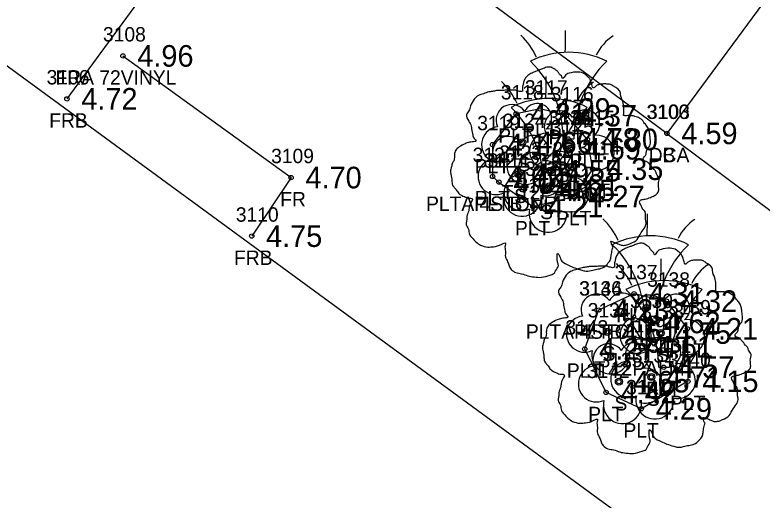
# Model space of a CAD drawing. Extents: x 2608598 to 2610682, y 641451 to 643526.
# Drawn here: x 2609915.7 to 2609967.6, y 642037.7 to 642071.3 of the extents above; entities that cross this region are included whole.
import ezdxf

# ---------------------------------------------------------------- set-up
doc = ezdxf.new("R2010")
doc.units = 0
for name, color, linetype in [('RD_EX_Bldg', 7, 'Continuous'), ('RD_EX_Bldg_txCode', 7, 'Continuous'), ('RD_EX_BldgApp', 7, 'Continuous'), ('RD_EX_BldgApp_txCode', 7, 'Continuous'), ('RD_EX_Conc', 7, 'Continuous'), ('RD_EX_Conc_txCode', 7, 'Continuous'), ('RD_EX_Fence_Other', 7, 'Continuous'), ('RD_EX_Fence_Other_txCode', 7, 'Continuous'), ('RD_EX_TX_Bldg_ELEV', 7, 'Continuous'), ('RD_EX_TX_BldgApp_ELEV', 7, 'Continuous'), ('RD_EX_TX_Conc_ELEV', 7, 'Continuous'), ('RD_EX_TX_Fence_Other_ELEV', 7, 'Continuous'), ('RD_EX_TX_VEG_ELEV', 7, 'Continuous'), ('RD_EX_VEG', 7, 'Continuous'), ('RD_EX_VEG_txCode', 7, 'Continuous'), ('RD_SMD_Locator', 7, 'Continuous')]:
    doc.layers.add(name, color=color, linetype=linetype)

msp = doc.modelspace()

# ---------------------------------------------------------------- linework, layer by layer
at = {"layer": 'RD_EX_Bldg'}
for points in [[(2609925.869, 642126.537), (2609978.853, 642087.305), (2609961.016, 642063.114), (2609908.032, 642102.345), (2609925.869, 642126.537)], [(2609909.121, 642072.222), (2609960.739, 642034.485), (2609938.692, 642004.745), (2609887.073, 642042.482), (2609909.121, 642072.222)]]:
    msp.add_lwpolyline(points, dxfattribs=at)
at = {"layer": 'RD_EX_BldgApp'}
for p, q in [((2609953.807, 642062.744), (2609954.557, 642062.744)), ((2609952.457, 642059.539), (2609953.207, 642059.539)), ((2609959.492, 642050.005), (2609960.242, 642050.005)), ((2609960.442, 642046.891), (2609961.192, 642046.891))]:
    msp.add_line(p, q, dxfattribs=at)
for points in [[(2609949.341, 642059.731), (2609951.701, 642058.031), (2609954.562, 642058.731), (2609955.861, 642060.629), (2609955.487, 642062.692), (2609954.03, 642064.344), (2609952.204, 642064.807), (2609950.538, 642064.47), (2609948.897, 642062.333), (2609948.903, 642060.121), (2609949.341, 642059.731)], [(2609956.277, 642050.851), (2609958.732, 642051.985), (2609960.983, 642051.466), (2609962.44, 642049.545), (2609962.47, 642045.898), (2609959.236, 642043.994), (2609956.787, 642045.128), (2609955.306, 642048.145), (2609956.277, 642050.851)]]:
    msp.add_lwpolyline(points, dxfattribs=at)
for centre, radius, start, end in [((2609916.101, 642070.082), 37.876, 358.0671, 0.2715), ((2609947.49, 642066.387), 4.895, 24.3279, 46.2665), ((2609959.071, 642067.137), 3.283, 123.2906, 154.4886), ((2609954.182, 642062.744), 5.997, 63.7794, 116.2206), ((2609946.307, 642062.744), 7.5, 0, 45.8366), ((2609962.057, 642062.744), 7.5, 134.1634, 180), ((2609914.75, 642066.877), 37.876, 358.0671, 0.2715), ((2609946.139, 642063.182), 4.895, 24.3279, 46.2665), ((2609957.72, 642063.933), 3.283, 123.2906, 154.4886), ((2609952.832, 642059.539), 5.997, 63.7794, 116.2206), ((2609944.957, 642059.539), 7.5, 0, 45.8366), ((2609960.707, 642059.539), 7.5, 134.1634, 180), ((2609953.175, 642053.648), 4.895, 24.3279, 46.2665), ((2609921.786, 642057.343), 37.876, 358.0671, 0.2715), ((2609964.756, 642054.398), 3.283, 123.2906, 154.4886), ((2609959.867, 642050.005), 5.997, 63.7794, 116.2206), ((2609951.992, 642050.005), 7.5, 0, 45.8366), ((2609967.742, 642050.005), 7.5, 134.1634, 180), ((2609954.125, 642050.534), 4.895, 24.3279, 46.2665), ((2609922.736, 642054.229), 37.876, 358.0671, 0.2715), ((2609965.705, 642051.284), 3.283, 123.2906, 154.4886), ((2609960.817, 642046.891), 5.997, 63.7794, 116.2206), ((2609952.942, 642046.891), 7.5, 0, 45.8366), ((2609968.692, 642046.891), 7.5, 134.1634, 180)]:
    msp.add_arc(centre, radius, start, end, dxfattribs=at)
at = {"layer": 'RD_EX_Conc'}
msp.add_lwpolyline([(2609961.016, 642063.114), (2609970.253, 642056.24), (2609973.77, 642053.725), (2609978.671, 642051.077), (2609980.569, 642050.362), (2609982.905, 642049.619), (2609986.846, 642049.978), (2609990.334, 642051.359), (2609992.677, 642052.953), (2609997.86, 642057.875), (2610001.755, 642060.528), (2610004.736, 642061.459), (2610008.347, 642061.293), (2610011.93, 642059.679), (2610016.967, 642054.45), (2610017.895, 642052.738)], dxfattribs=at)
at = {"layer": 'RD_EX_Fence_Other'}
msp.add_line((2609932.063, 642082.907), (2609919.333, 642065.511), dxfattribs=at)
msp.add_lwpolyline([(2609923.224, 642068.493), (2609934.905, 642060.046), (2609932.168, 642055.98)], dxfattribs=at)
at = {"layer": 'RD_EX_VEG'}
for centre, radius in [((2609950.956, 642062.485), 0.25), ((2609954.298, 642062.045), 0.25), ((2609952.914, 642060.524), 0.25), ((2609950.711, 642060.278), 0.25), ((2609952.901, 642060.506), 0.0001), ((2609952.511, 642059.16), 0.25), ((2609956.856, 642049.333), 0.25), ((2609960.568, 642049.251), 0.25), ((2609959.304, 642048.295), 0.25), ((2609959.291, 642048.276), 0.0001), ((2609959.93, 642046.198), 0.25), ((2609957.68, 642045.875), 0.25)]:
    msp.add_circle(centre, radius, dxfattribs=at)
for centre, radius, start, end in [((2609950.235, 642064.032), 1.084, 34.9763, 204.756), ((2609952.002, 642064.187), 0.995, 308.7626, 152.0467), ((2609953.577, 642063.592), 1.084, 34.9763, 204.756), ((2609955.343, 642063.747), 0.995, 308.7626, 152.0467), ((2609949.393, 642062.329), 1.257, 96.4518, 294.734), ((2609952.796, 642062.206), 1.218, 256.5667, 98.1046), ((2609949.99, 642061.825), 1.084, 34.9763, 204.756), ((2609951.756, 642061.98), 0.995, 308.7626, 152.0467), ((2609952.734, 642061.889), 1.257, 96.4518, 294.734), ((2609956.137, 642061.765), 1.218, 256.5667, 98.1046), ((2609951.79, 642060.707), 1.084, 34.9763, 204.756), ((2609953.556, 642060.862), 0.995, 308.7626, 152.0467), ((2609949.147, 642060.122), 1.257, 96.4518, 294.734), ((2609951.202, 642060.889), 1.318, 166.8827, 5.7589), ((2609952.551, 642059.998), 1.218, 256.5667, 98.1046), ((2609954.543, 642060.448), 1.318, 166.8827, 5.7589), ((2609950.947, 642059.005), 1.257, 96.4518, 294.734), ((2609954.351, 642058.881), 1.218, 256.5667, 98.1046), ((2609950.957, 642058.681), 1.318, 166.8827, 5.7589), ((2609952.756, 642057.564), 1.318, 166.8827, 5.7589), ((2609956.135, 642050.88), 1.084, 34.9763, 204.756), ((2609957.902, 642051.035), 0.995, 308.7626, 152.0467), ((2609961.614, 642050.953), 0.995, 308.7626, 152.0467), ((2609959.847, 642050.798), 1.084, 34.9763, 204.756), ((2609955.293, 642049.178), 1.257, 96.4518, 294.734), ((2609959.005, 642049.096), 1.257, 96.4518, 294.734), ((2609958.696, 642049.054), 1.218, 256.5667, 98.1046), ((2609962.408, 642048.972), 1.218, 256.5667, 98.1046), ((2609959.209, 642047.745), 1.084, 34.9763, 204.756), ((2609960.975, 642047.9), 0.995, 308.7626, 152.0467), ((2609956.959, 642047.422), 1.084, 34.9763, 204.756), ((2609958.725, 642047.577), 0.995, 308.7626, 152.0467), ((2609957.102, 642047.737), 1.318, 166.8827, 5.7589), ((2609960.814, 642047.655), 1.318, 166.8827, 5.7589), ((2609958.366, 642046.043), 1.257, 96.4518, 294.734), ((2609956.116, 642045.72), 1.257, 96.4518, 294.734), ((2609959.519, 642045.596), 1.218, 256.5667, 98.1046), ((2609961.77, 642045.919), 1.218, 256.5667, 98.1046), ((2609960.176, 642044.602), 1.318, 166.8827, 5.7589), ((2609957.925, 642044.279), 1.318, 166.8827, 5.7589)]:
    msp.add_arc(centre, radius, start, end, dxfattribs=at)
for points in [[(2609953.046, 642067.692), (2609952.746, 642067.717), (2609952.421, 642067.617), (2609952.171, 642067.517), (2609951.946, 642067.442), (2609951.721, 642067.342), (2609951.422, 642067.167), (2609951.197, 642066.967), (2609951.072, 642066.717), (2609951.022, 642066.492), (2609950.972, 642066.217), (2609950.972, 642066.042), (2609950.847, 642066.017), (2609950.697, 642066.042), (2609950.447, 642066.117), (2609950.197, 642066.117), (2609949.947, 642066.117), (2609949.597, 642066.092), (2609949.247, 642066.092), (2609948.973, 642066.042), (2609948.648, 642065.992), (2609948.273, 642065.867), (2609947.923, 642065.742), (2609947.623, 642065.493), (2609947.373, 642065.018), (2609947.248, 642064.668), (2609947.098, 642064.418), (2609947.248, 642063.968), (2609947.423, 642063.618), (2609947.448, 642063.418), (2609947.523, 642062.994), (2609947.623, 642062.769), (2609947.748, 642062.569), (2609947.673, 642062.544), (2609947.298, 642062.494), (2609946.998, 642062.394), (2609946.574, 642062.169), (2609946.349, 642061.944), (2609946.249, 642061.619), (2609946.224, 642061.269), (2609946.124, 642061.07), (2609946.049, 642060.795), (2609946.024, 642060.72), (2609945.974, 642060.395), (2609946.074, 642059.945), (2609946.099, 642059.595), (2609946.224, 642059.37), (2609946.374, 642059.195), (2609946.549, 642058.945), (2609946.948, 642058.721), (2609947.273, 642058.621), (2609947.473, 642058.596), (2609947.298, 642058.096), (2609947.248, 642057.746), (2609947.123, 642057.346), (2609947.123, 642057.271), (2609947.073, 642056.796), (2609947.223, 642056.471), (2609947.298, 642056.097), (2609947.473, 642055.872), (2609947.748, 642055.572), (2609948.073, 642055.347), (2609948.573, 642055.222), (2609948.973, 642055.247), (2609949.547, 642055.422), (2609949.797, 642055.497), (2609949.772, 642055.322), (2609949.797, 642054.947), (2609949.797, 642054.522), (2609949.947, 642054.198), (2609950.047, 642053.923), (2609950.197, 642053.673), (2609950.522, 642053.448), (2609950.922, 642053.373), (2609951.347, 642053.223), (2609951.796, 642053.148), (2609952.296, 642053.123), (2609952.896, 642053.273), (2609953.171, 642053.398), (2609953.271, 642053.573), (2609953.471, 642053.948), (2609953.421, 642054.173), (2609953.446, 642054.772), (2609953.546, 642054.597), (2609953.721, 642054.247), (2609954.22, 642053.948), (2609954.62, 642053.773), (2609955.095, 642053.623), (2609955.395, 642053.548), (2609955.87, 642053.623), (2609956.244, 642053.698), (2609956.619, 642053.823), (2609956.919, 642054.098), (2609957.094, 642054.372), (2609957.144, 642054.647), (2609957.219, 642055.022), (2609957.269, 642055.197)], [(2609957.269, 642055.197), (2609957.194, 642055.372), (2609957.144, 642055.622), (2609957.219, 642055.597), (2609957.394, 642055.547), (2609957.669, 642055.422), (2609957.894, 642055.347), (2609958.219, 642055.372), (2609958.493, 642055.472), (2609958.943, 642055.747), (2609959.218, 642056.222), (2609959.493, 642056.621), (2609959.568, 642056.946), (2609959.518, 642057.171), (2609959.493, 642057.671), (2609959.293, 642057.921), (2609959.243, 642058.046), (2609959.143, 642058.446), (2609959.218, 642058.496), (2609959.493, 642058.546), (2609959.868, 642058.671), (2609960.143, 642058.795), (2609960.368, 642058.97), (2609960.443, 642059.195), (2609960.418, 642059.595), (2609960.468, 642059.995), (2609960.393, 642060.145), (2609960.293, 642060.295), (2609960.218, 642060.495), (2609960.068, 642060.645), (2609959.968, 642060.795), (2609959.868, 642060.895), (2609959.743, 642061.045), (2609959.568, 642061.169), (2609959.418, 642061.219), (2609959.368, 642061.369), (2609959.518, 642061.569), (2609959.568, 642061.669), (2609959.593, 642061.894), (2609959.818, 642062.244), (2609959.868, 642062.644), (2609959.818, 642063.069), (2609959.768, 642063.344), (2609959.618, 642063.618), (2609959.418, 642063.868), (2609959.293, 642064.043), (2609959.118, 642064.168), (2609958.793, 642064.293), (2609958.543, 642064.343), (2609958.194, 642064.343), (2609957.994, 642064.393), (2609958.019, 642064.443), (2609958.019, 642064.593), (2609958.019, 642064.868), (2609957.944, 642065.318), (2609957.794, 642065.817), (2609957.794, 642065.842), (2609957.694, 642066.092), (2609957.469, 642066.292), (2609957.294, 642066.392), (2609957.094, 642066.517), (2609956.844, 642066.542), (2609956.544, 642066.542), (2609956.269, 642066.492), (2609956.069, 642066.392), (2609955.895, 642066.267), (2609955.82, 642066.417), (2609955.72, 642066.717), (2609955.67, 642066.867), (2609955.52, 642067.042), (2609955.295, 642067.242), (2609954.845, 642067.367), (2609954.22, 642067.292), (2609953.92, 642067.092), (2609953.77, 642066.917), (2609953.721, 642067.042), (2609953.521, 642067.242), (2609953.421, 642067.417), (2609953.246, 642067.542), (2609953.096, 642067.642), (2609952.996, 642067.692)], [(2609959.435, 642055.462), (2609959.136, 642055.487), (2609958.811, 642055.387), (2609958.561, 642055.287), (2609958.336, 642055.212), (2609958.111, 642055.112), (2609957.811, 642054.937), (2609957.586, 642054.737), (2609957.461, 642054.487), (2609957.411, 642054.262), (2609957.361, 642053.988), (2609957.361, 642053.813), (2609957.236, 642053.788), (2609957.086, 642053.813), (2609956.837, 642053.888), (2609956.587, 642053.888), (2609956.337, 642053.888), (2609955.987, 642053.863), (2609955.637, 642053.863), (2609955.362, 642053.813), (2609955.037, 642053.763), (2609954.663, 642053.638), (2609954.313, 642053.513), (2609954.013, 642053.263), (2609953.763, 642052.788), (2609953.638, 642052.438), (2609953.488, 642052.188), (2609953.638, 642051.739), (2609953.813, 642051.389), (2609953.838, 642051.189), (2609953.913, 642050.764), (2609954.013, 642050.539), (2609954.138, 642050.339), (2609954.063, 642050.314), (2609953.688, 642050.264), (2609953.388, 642050.164), (2609952.963, 642049.939), (2609952.738, 642049.714), (2609952.638, 642049.39), (2609952.613, 642049.04), (2609952.514, 642048.84), (2609952.439, 642048.565), (2609952.414, 642048.49), (2609952.364, 642048.165), (2609952.464, 642047.715), (2609952.489, 642047.365), (2609952.613, 642047.141), (2609952.763, 642046.966), (2609952.938, 642046.716), (2609953.338, 642046.491), (2609953.663, 642046.391), (2609953.863, 642046.366), (2609953.688, 642045.866), (2609953.638, 642045.516), (2609953.513, 642045.116), (2609953.513, 642045.042), (2609953.463, 642044.567), (2609953.613, 642044.242), (2609953.688, 642043.867), (2609953.863, 642043.642), (2609954.138, 642043.342), (2609954.463, 642043.117), (2609954.962, 642042.992), (2609955.362, 642043.017), (2609955.937, 642043.192), (2609956.187, 642043.267), (2609956.162, 642043.092), (2609956.187, 642042.717), (2609956.187, 642042.293), (2609956.337, 642041.968), (2609956.437, 642041.693), (2609956.587, 642041.443), (2609956.912, 642041.218), (2609957.311, 642041.143), (2609957.736, 642040.993), (2609958.186, 642040.918), (2609958.686, 642040.893), (2609959.286, 642041.043), (2609959.56, 642041.168), (2609959.66, 642041.343), (2609959.86, 642041.718), (2609959.81, 642041.943), (2609959.835, 642042.543), (2609959.935, 642042.368), (2609960.11, 642042.018), (2609960.61, 642041.718), (2609961.01, 642041.543), (2609961.485, 642041.393), (2609961.784, 642041.318), (2609962.259, 642041.393), (2609962.634, 642041.468), (2609963.009, 642041.593), (2609963.309, 642041.868), (2609963.484, 642042.143), (2609963.534, 642042.418), (2609963.609, 642042.792), (2609963.659, 642042.967)], [(2609963.659, 642042.967), (2609963.584, 642043.142), (2609963.534, 642043.392), (2609963.609, 642043.367), (2609963.784, 642043.317), (2609964.058, 642043.192), (2609964.283, 642043.117), (2609964.608, 642043.142), (2609964.883, 642043.242), (2609965.333, 642043.517), (2609965.608, 642043.992), (2609965.883, 642044.392), (2609965.958, 642044.717), (2609965.908, 642044.942), (2609965.883, 642045.441), (2609965.683, 642045.691), (2609965.633, 642045.816), (2609965.533, 642046.216), (2609965.608, 642046.266), (2609965.883, 642046.316), (2609966.257, 642046.441), (2609966.532, 642046.566), (2609966.757, 642046.741), (2609966.832, 642046.966), (2609966.807, 642047.365), (2609966.857, 642047.765), (2609966.782, 642047.915), (2609966.682, 642048.065), (2609966.607, 642048.265), (2609966.457, 642048.415), (2609966.357, 642048.565), (2609966.257, 642048.665), (2609966.133, 642048.815), (2609965.958, 642048.94), (2609965.808, 642048.99), (2609965.758, 642049.14), (2609965.908, 642049.34), (2609965.958, 642049.44), (2609965.983, 642049.664), (2609966.208, 642050.014), (2609966.257, 642050.414), (2609966.208, 642050.839), (2609966.158, 642051.114), (2609966.008, 642051.389), (2609965.808, 642051.639), (2609965.683, 642051.814), (2609965.508, 642051.938), (2609965.183, 642052.063), (2609964.933, 642052.113), (2609964.583, 642052.113), (2609964.383, 642052.163), (2609964.408, 642052.213), (2609964.408, 642052.363), (2609964.408, 642052.638), (2609964.333, 642053.088), (2609964.183, 642053.588), (2609964.183, 642053.613), (2609964.083, 642053.863), (2609963.859, 642054.063), (2609963.684, 642054.162), (2609963.484, 642054.287), (2609963.234, 642054.312), (2609962.934, 642054.312), (2609962.659, 642054.262), (2609962.459, 642054.162), (2609962.284, 642054.038), (2609962.209, 642054.187), (2609962.109, 642054.487), (2609962.059, 642054.637), (2609961.909, 642054.812), (2609961.685, 642055.012), (2609961.235, 642055.137), (2609960.61, 642055.062), (2609960.31, 642054.862), (2609960.16, 642054.687), (2609960.11, 642054.812), (2609959.91, 642055.012), (2609959.81, 642055.187), (2609959.635, 642055.312), (2609959.485, 642055.412), (2609959.385, 642055.462)]]:
    msp.add_spline(points, degree=3, dxfattribs=at)
at = {"layer": 'RD_SMD_Locator'}
for centre in [(2609923.224, 642068.493), (2609919.333, 642065.511), (2609952.204, 642064.807), (2609950.538, 642064.47), (2609954.03, 642064.344), (2609954.154, 642062.726), (2609955.487, 642062.692), (2609961.016, 642063.114), (2609961.016, 642063.114), (2609948.897, 642062.333), (2609950.956, 642062.485), (2609954.298, 642062.045), (2609955.861, 642060.629), (2609948.903, 642060.121), (2609950.711, 642060.278), (2609952.914, 642060.524), (2609934.905, 642060.046), (2609949.341, 642059.731), (2609949.341, 642059.731), (2609952.511, 642059.16), (2609952.804, 642059.521), (2609954.562, 642058.731), (2609951.701, 642058.031), (2609932.168, 642055.98), (2609958.732, 642051.985), (2609960.983, 642051.466), (2609956.277, 642050.851), (2609956.277, 642050.851), (2609959.839, 642049.987), (2609956.856, 642049.333), (2609960.568, 642049.251), (2609962.44, 642049.545), (2609955.306, 642048.145), (2609959.304, 642048.295), (2609960.789, 642046.873), (2609959.93, 642046.198), (2609957.68, 642045.875), (2609962.47, 642045.898), (2609956.787, 642045.128), (2609959.236, 642043.994)]:
    msp.add_circle(centre, 0.15, dxfattribs=at)

# ---------------------------------------------------------------- texts
at = {"layer": 'RD_EX_Bldg_txCode'}
for s, p in [('3100', (2609959.591, 642064.114)), ('B', (2609960.709, 642061.114))]:
    msp.add_text(s, height=1, dxfattribs=at).set_placement(p)
at = {"layer": 'RD_EX_BldgApp_txCode'}
for s, p in [('3118', (2609949.475, 642065.47)), ('3117', (2609951.141, 642065.807)), ('3116', (2609952.943, 642065.344)), ('3126', (2609952.784, 642063.726)), ('3115', (2609954.424, 642063.692)), ('3119', (2609947.834, 642063.333)), ('PLT', (2609949.294, 642062.47)), ('PLT', (2609950.96, 642062.807)), ('PLT', (2609952.786, 642062.344)), ('3114', (2609954.798, 642061.629)), ('3120', (2609947.517, 642061.121)), ('PLT', (2609947.653, 642060.333)), ('3121', (2609948.278, 642060.731)), ('3111', (2609948.561, 642060.731)), ('3127', (2609951.458, 642060.521)), ('FLT', (2609952.934, 642060.726)), ('PLT', (2609954.243, 642060.692)), ('3113', (2609953.499, 642059.731)), ('3112', (2609950.638, 642059.031)), ('PLT', (2609954.617, 642058.629)), ('PLTA 4STONE', (2609944.282, 642057.731)), ('PLTB', (2609947.624, 642057.731)), ('PLT', (2609947.659, 642058.121)), ('FLT', (2609951.584, 642057.521)), ('PLT', (2609953.318, 642056.731)), ('PLT', (2609950.457, 642056.031)), ('3137', (2609957.386, 642052.985)), ('3138', (2609959.637, 642052.466)), ('3136', (2609954.907, 642051.851)), ('3144', (2609954.931, 642051.851)), ('3130', (2609958.454, 642050.987)), ('3139', (2609961.093, 642050.545)), ('PLT', (2609957.488, 642049.985)), ('PLT', (2609959.739, 642049.466)), ('PLTA 4STONE', (2609951.218, 642048.851)), ('3143', (2609953.959, 642049.145)), ('PLTB', (2609954.561, 642048.851)), ('FLT', (2609958.619, 642047.987)), ('3131', (2609959.726, 642047.873)), ('PLT', (2609961.196, 642047.545)), ('3140', (2609961.084, 642046.898)), ('PLT', (2609954.062, 642046.145)), ('3142', (2609955.44, 642046.128)), ('3141', (2609958.173, 642044.994)), ('FLT', (2609959.569, 642044.873)), ('PLT', (2609961.226, 642043.898)), ('PLT', (2609955.543, 642043.128)), ('PLT', (2609957.992, 642041.994))]:
    msp.add_text(s, height=1, dxfattribs=at).set_placement(p)
at = {"layer": 'RD_EX_Conc_txCode'}
for s, p in [('3103', (2609959.631, 642064.114)), ('DCA', (2609959.749, 642061.114))]:
    msp.add_text(s, height=1, dxfattribs=at).set_placement(p)
at = {"layer": 'RD_EX_Fence_Other_txCode'}
for s, p in [('3108', (2609921.838, 642069.493)), ('3106', (2609917.923, 642066.511)), ('FRA 72VINYL', (2609918.539, 642066.493)), ('FRB', (2609918.104, 642063.511)), ('3109', (2609933.519, 642061.046)), ('FR', (2609934.149, 642058.046)), ('3110', (2609931.066, 642056.98)), ('FRB', (2609930.94, 642053.98))]:
    msp.add_text(s, height=1, dxfattribs=at).set_placement(p)
at = {"layer": 'RD_EX_TX_Bldg_ELEV'}
msp.add_text('4.59', height=1.5, dxfattribs=at).set_placement((2609962.016, 642062.364))
at = {"layer": 'RD_EX_TX_BldgApp_ELEV'}
for s, p in [('4.29', (2609953.204, 642064.057)), ('4.21', (2609951.538, 642063.72)), ('4.37', (2609955.03, 642063.594)), ('4.78', (2609955.154, 642061.976)), ('4.30', (2609956.487, 642061.942)), ('4.17', (2609949.897, 642061.583)), ('4.35', (2609956.861, 642059.879)), ('4.02', (2609949.903, 642059.371)), ('4.01', (2609950.341, 642058.981)), ('4.01', (2609950.341, 642058.981)), ('4.61', (2609953.804, 642058.771)), ('4.27', (2609955.562, 642057.981)), ('4.21', (2609952.701, 642057.281)), ('4.31', (2609959.732, 642051.235)), ('4.32', (2609961.983, 642050.716)), ('4.23', (2609957.277, 642050.101)), ('4.23', (2609957.277, 642050.101)), ('4.62', (2609960.839, 642049.237)), ('4.21', (2609963.44, 642048.795)), ('4.27', (2609956.306, 642047.395)), ('4.57', (2609961.789, 642046.123)), ('4.15', (2609963.47, 642045.148)), ('4.42', (2609957.787, 642044.378)), ('4.29', (2609960.236, 642043.244))]:
    msp.add_text(s, height=1.5, dxfattribs=at).set_placement(p)
at = {"layer": 'RD_EX_TX_Conc_ELEV'}
msp.add_text('4.59', height=1.5, dxfattribs=at).set_placement((2609962.016, 642062.364))
at = {"layer": 'RD_EX_TX_Fence_Other_ELEV'}
for s, p in [('4.96', (2609924.224, 642067.743)), ('4.72', (2609920.333, 642064.761)), ('4.70', (2609935.905, 642059.296)), ('4.75', (2609933.168, 642055.23))]:
    msp.add_text(s, height=1.5, dxfattribs=at).set_placement(p)
at = {"layer": 'RD_EX_TX_VEG_ELEV'}
for s, p in [('4.66', (2609951.956, 642061.735)), ('4.69', (2609955.298, 642061.295)), ('4.55', (2609953.914, 642059.774)), ('4.59', (2609951.711, 642059.528)), ('4.65', (2609953.511, 642058.41)), ('4.61', (2609957.856, 642048.583)), ('4.75', (2609961.568, 642048.501)), ('4.61', (2609960.304, 642047.545)), ('4.71', (2609960.93, 642045.448)), ('4.65', (2609958.68, 642045.125))]:
    msp.add_text(s, height=1.5, dxfattribs=at).set_placement(p)
at = {"layer": 'RD_EX_VEG_txCode'}
for s, p in [('3124', (2609949.61, 642063.485)), ('3125', (2609952.951, 642063.045)), ('3123', (2609949.365, 642061.278)), ('3128', (2609951.567, 642061.524)), ('S', (2609950.649, 642060.485)), ('3122', (2609951.164, 642060.16)), ('S', (2609953.991, 642060.045)), ('T 12PALM', (2609949.544, 642058.524)), ('S', (2609950.404, 642058.278)), ('S', (2609952.204, 642057.16)), ('3134', (2609955.51, 642050.333)), ('3133', (2609959.222, 642050.251)), ('3129', (2609957.957, 642049.295)), ('S', (2609956.549, 642047.333)), ('3135', (2609956.333, 642046.875)), ('3132', (2609958.584, 642047.198)), ('S', (2609960.261, 642047.251)), ('T 12PALM', (2609955.933, 642046.295)), ('S', (2609959.623, 642044.198)), ('S', (2609957.373, 642043.875))]:
    msp.add_text(s, height=1, dxfattribs=at).set_placement(p)

doc.saveas('drawing.dxf')
